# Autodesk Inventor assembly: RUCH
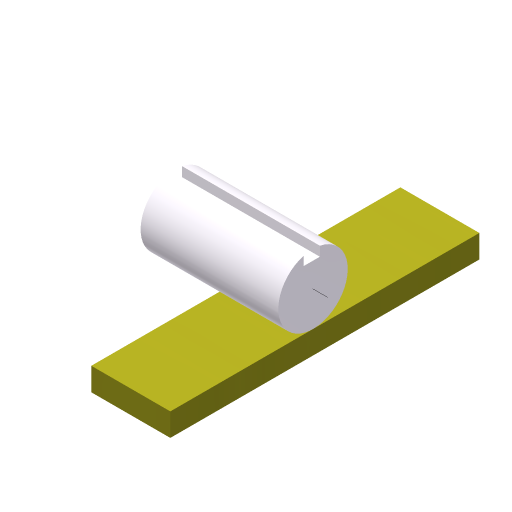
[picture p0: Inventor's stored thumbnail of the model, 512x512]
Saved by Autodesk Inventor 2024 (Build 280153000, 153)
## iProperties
Created: 2023-03
Part Number: RUCH
Document SubType Name: Assembly
Designer: Andrzej Jaskulski
Manufacturer: Standard
Standards Organization: Custom
Checked By: A.J.
Engr Approved By: Andrzej Jaskulski
Mfg Approved By: Andrzej Jaskulski
Authority: A.J.
Company: ATC
Title: A.J.: Kurs R2024-MEP
Author: Andrzej Jaskulski
Revision Number: 1/24
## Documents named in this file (3)
- C:\Users\AndJas\Documents\R2024-MEP\Obszar roboczy\RUCH.iam
- C:\Users\AndJas\Documents\R2024-MEP\Obszar roboczy\RUCH-Listwa.ipt
- C:\Users\AndJas\Documents\R2024-MEP\Obszar roboczy\RUCH-Koło.ipt
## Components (2 placed, 2 different names)
1. RUCH-Listwa:1 — Styczności, Równoległość-CZÓŁ, Równoległość Do YZ, Kąt z XY, Obrót/przesunięcie:1
2. RUCH-Koło:1 — Styczności, Równoległość-CZÓŁ, Kątowe NAPĘDOWE, Zestawiające z Osią X, Obrót/przesunięcie:1
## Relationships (7: Flush 2, Angle 2, Tangent 1, Mate 1, RelateRotateTranslate 1)
- Styczności [Tangent]: RUCH-Listwa:1 ↔ RUCH-Koło:1
- Równoległość-CZÓŁ [Flush]: RUCH-Listwa:1 ↔ RUCH-Koło:1
- Kątowe NAPĘDOWE [Angle]: RUCH-Koło:1
- Zestawiające z Osią X [Mate]: RUCH-Koło:1
- Równoległość Do YZ [Flush]: RUCH-Listwa:1
- Kąt z XY [Angle]: RUCH-Listwa:1
- Obrót/przesunięcie:1 [RelateRotateTranslate]: RUCH-Listwa:1 ↔ RUCH-Koło:1
## Named parameters: OBWÓD = 94.2 mm
